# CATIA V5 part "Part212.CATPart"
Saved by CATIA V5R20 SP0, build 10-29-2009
Part number: FA 168700-1
Revision: ANY
Definition: UNKNOWN
Nomenclature: FA 168700-1
Source: Unknown
Bounding box of the stored display mesh (mm): x -3.804 to 3.804, y 0.28 to 2.5, z -4 to 4
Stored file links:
  C:\Users\Utente\Desktop\IO LAVORO\3D X SITO CF\CUMSA\3D files FA\FA 200700\Part212.CATPart
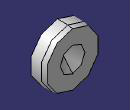
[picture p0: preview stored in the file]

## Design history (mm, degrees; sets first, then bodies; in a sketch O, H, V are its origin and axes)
Body1 "Cortar-Extruir1" (main body)
  Solid1: solid without history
